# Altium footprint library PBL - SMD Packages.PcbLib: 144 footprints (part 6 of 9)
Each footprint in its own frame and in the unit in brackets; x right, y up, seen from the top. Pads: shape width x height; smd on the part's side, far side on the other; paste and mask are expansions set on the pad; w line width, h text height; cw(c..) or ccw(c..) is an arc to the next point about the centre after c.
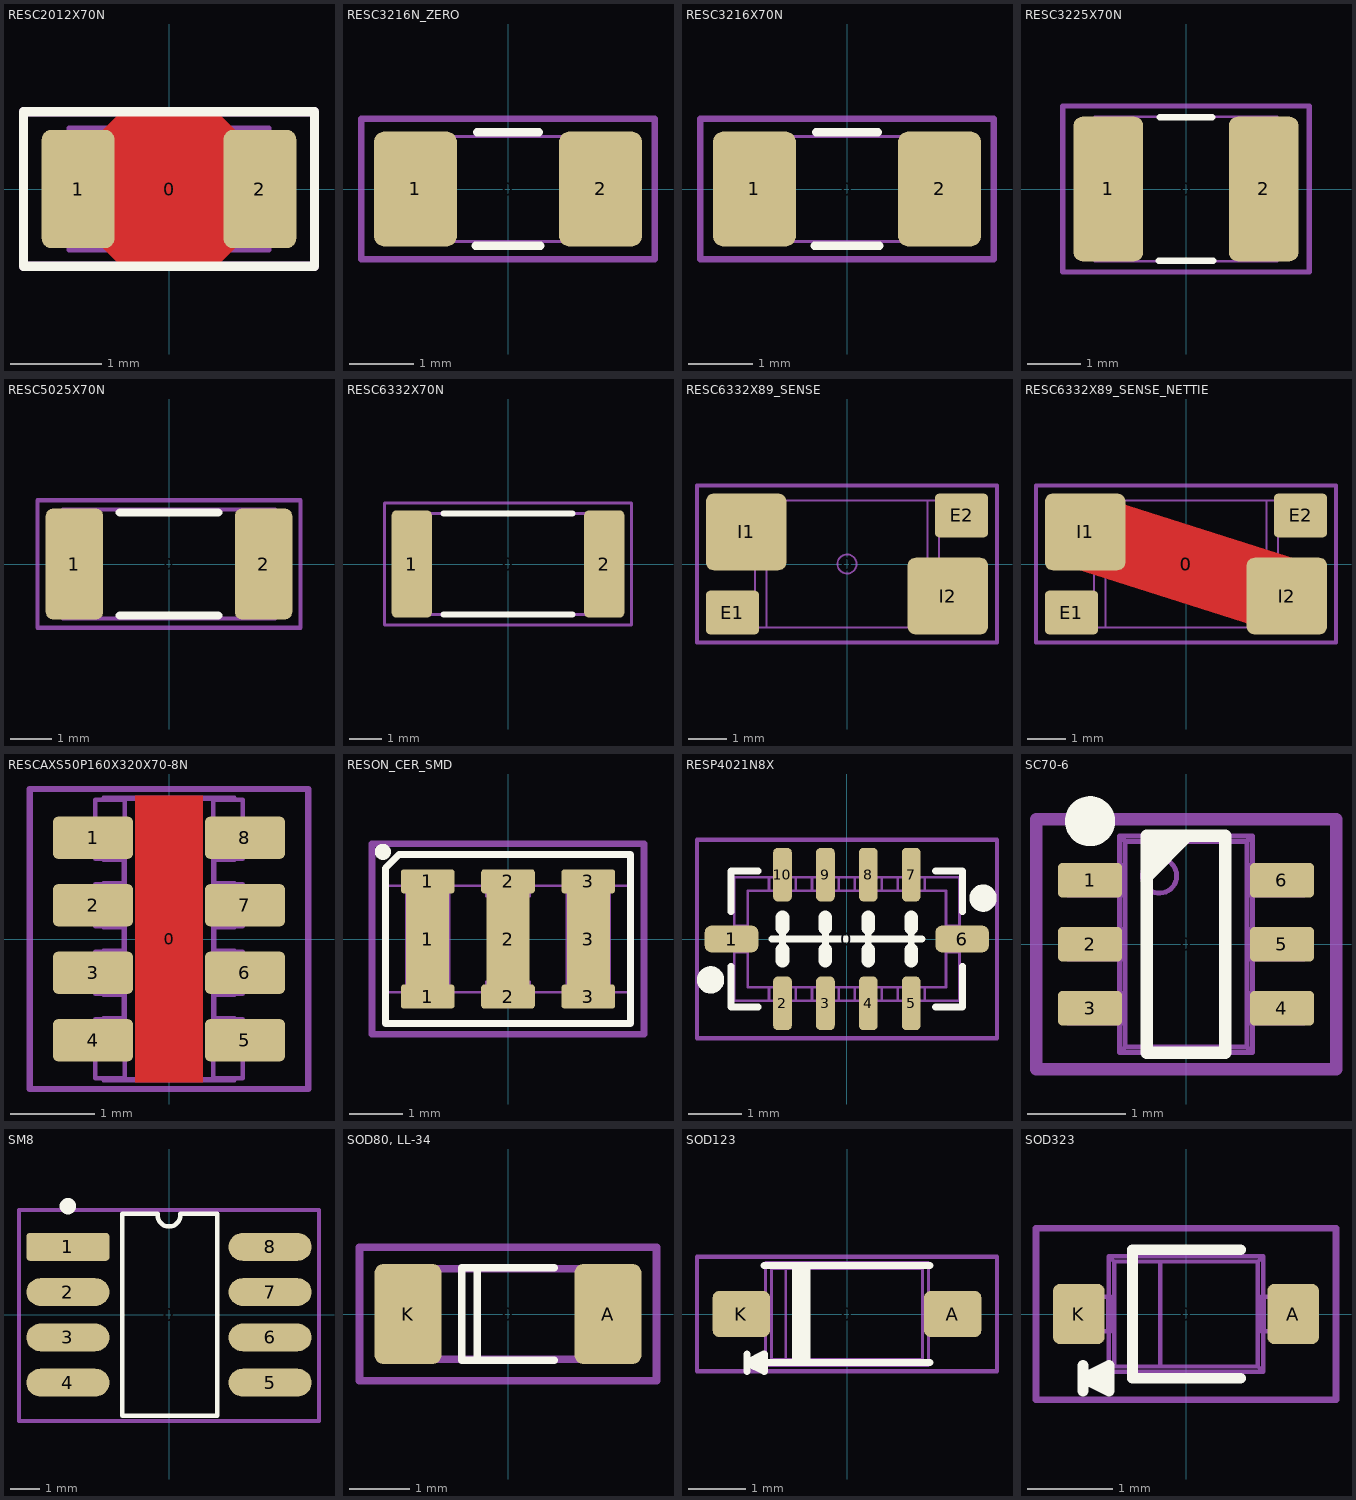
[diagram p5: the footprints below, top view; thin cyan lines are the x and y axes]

## RESC2012X70N [mm] "Chip Resistor, Body 2.0x1.2mm, EIA 0805, IPC Medium Density"
height 0.7
pads (3):
  round 0.254 on Mech15: 0(0,0)
  rrect25% 0.8x1.3 smd: 1(-1,0) 2(1,0)
Top Layer:
  pour cut-out: -0.725,0.65 -0.525,0.85 0.525,0.85 0.725,0.65 0.725,-0.65 0.525,-0.85 -0.525,-0.85 -0.725,-0.65
Top Overlay:
  lines w0.1: -1.6,-0.85 -1.6,0.85 1.6,0.85 1.6,-0.85 -1.6,-0.85
08 - Top ASM Des:
  text ".Designator" at -1.325,-0.325 h1
13 - 3D Top Side:
  lines w0.05: 0.6,-0.674 -0.6,-0.674 ; -0.6,-0.675 -0.6,0.675 -1.1,0.675 -1.1,-0.675 -0.6,-0.675 ; -0.6,-0.674 0.6,-0.674 ; 0.6,-0.675 0.6,0.675 ; 0.6,-0.675 1.1,-0.675 1.1,0.675 0.6,0.675 ; 0.6,0.674 -0.6,0.674 0.6,0.674
15 - Top Courtyards:
  lines w0.1: -1.6,-0.85 1.6,-0.85 1.6,0.85 -1.6,0.85 -1.6,-0.85
3D body "RES 0805 (2012 metric).STEP": height 0.69, standoff -0.01, extent -1.1,-0.675 1.1,0.675

## RESC3216N_ZERO [mm] "Chip Resistor, Body 3.2x1.6mm, 1206, IPC Medium Density"
height 0.7
pads (3):
  round 0.508 on Mech15: 0(0,0)
  rrect25% 1.3x1.8 smd: 1(-1.45,0) 2(1.45,0)
Top Overlay:
  lines w0.127: -0.508,-0.889 0.508,-0.889 ; -0.483,0.889 0.483,0.889
13 - 3D Top Side:
  lines w0.05: 1.025,-0.824 -1.025,-0.824 1.025,-0.824 ; -1.625,-0.825 -1.025,-0.825 -1.025,0.825 -1.625,0.825 -1.625,-0.825 ; -1.025,0.824 1.025,0.824 -1.025,0.824 ; 1.025,-0.825 1.025,0.825 1.625,0.825 1.625,-0.825 1.025,-0.825
15 - Top Courtyards:
  lines w0.1: -2.3,-1.1 -2.3,1.1 2.3,1.1 2.3,-1.1 -2.3,-1.1
3D body "RES 1206 (3216 metric).STEP": height 0.69, standoff -0.01, extent -1.625,-0.825 1.625,0.825

## RESC3216X70N [mm] "Chip Resistor, Body 3.2x1.6mm, EIA 1206, IPC Medium Density"
height 0.7
pads (3):
  round 0.508 on Mech15: 0(0,0)
  rrect25% 1.3x1.8 smd: 1(-1.45,0) 2(1.45,0)
Top Overlay:
  lines w0.127: -0.508,-0.889 0.508,-0.889 ; -0.483,0.889 0.483,0.889
13 - 3D Top Side:
  lines w0.05: 1.025,-0.824 -1.025,-0.824 1.025,-0.824 ; -1.625,-0.825 -1.025,-0.825 -1.025,0.825 -1.625,0.825 -1.625,-0.825 ; -1.025,0.824 1.025,0.824 -1.025,0.824 ; 1.025,-0.825 1.025,0.825 1.625,0.825 1.625,-0.825 1.025,-0.825
15 - Top Courtyards:
  lines w0.1: -2.3,-1.1 -2.3,1.1 2.3,1.1 2.3,-1.1 -2.3,-1.1
3D body "RES 1206 (3216 metric).STEP": height 0.69, standoff -0.01, extent -1.625,-0.825 1.625,0.825

## RESC3225X70N [mm] "Chip Resistor, Body 3.2x2.5mm, EIA 1210, IPC Medium Density"
height 0.7
pads (3):
  round 0.508 on Mech15: 0(0,0)
  rrect25% 1.3x2.7 smd: 1(-1.45,0) 2(1.45,0)
Top Overlay:
  lines w0.127: -0.508,-1.339 0.508,-1.339 ; -0.483,1.339 0.483,1.339
13 - 3D Top Side:
  lines w0.05: -1.7,-1.35 -1.1,-1.35 -1.1,1.35 -1.7,1.35 -1.7,-1.35 ; -1.1,-1.349 1.1,-1.349 -1.1,-1.349 ; -1.1,1.349 1.1,1.349 -1.1,1.349 ; 1.1,-1.35 1.1,1.35 1.7,1.35 1.7,-1.35 1.1,-1.35
15 - Top Courtyards:
  lines w0.1: -2.3,-1.55 -2.3,1.55 2.3,1.55 2.3,-1.55 -2.3,-1.55
3D body "RES 1210 (3225 metric).STEP": height 0.69, standoff -0.01, extent -1.7,-1.35 1.7,1.35

## RESC5025X70N [mm] "Chip Resistor, Body 5.0x2.5mm, 2010, IPC Medium Density"
height 0.7
pads (3):
  round 0.508 on Mech15: 0(0,0)
  rrect25% 1.4x2.7 smd: 1(-2.3,0) 2(2.3,0)
Top Overlay:
  lines w0.2: -1.2,-1.25 1.2,-1.25 ; -1.2,1.25 1.2,1.25
13 - 3D Top Side:
  lines w0.1: -2.575,-1.325 -2.575,1.325 2.575,1.325 2.575,-1.325 -2.575,-1.325
15 - Top Courtyards:
  lines w0.1: -3.2,-1.55 -3.2,1.55 3.2,1.55 3.2,-1.55 -3.2,-1.55
3D body "RES 2010 (5025 metric).STEP": height 0.69, standoff -0.01, extent -2.6,-1.35 2.6,1.35

## RESC6332X70N [mm] "Chip Resistor, Body 6.3x3.2mm, 2512, IPC Medium Density"
height 0.7
pads (3):
  round 1 on Mech15: 0(0,0)
  rrect25% 1.25x3.35 smd: 1(-3,0) 2(3,0)
Top Overlay:
  lines w0.2: -2,-1.575 2,-1.575 ; -2,1.575 2,1.575
13 - 3D Top Side:
  lines w0.1: -3.15,-1.575 -3.15,1.575 3.15,1.575 3.15,-1.575 -3.15,-1.575
15 - Top Courtyards:
  lines w0.1: -3.85,-1.9 -3.85,1.9 3.85,1.9 3.85,-1.9 -3.85,-1.9
3D body "RES 2512 (6432 metric).STEP": height 0.69, standoff -0.01, extent -3.3,-1.7 3.3,1.7

## RESC6332X89_SENSE [mil] "SMD Sense Resistor with Kelvin terminations, Body 6.3x3.2mm, 2512, IPC Medium Density"
height 35.04
pads (5):
  round 39.37 on Mech15: 0(0,0)
  rrect20% 55x45 smd paste-27.56: E1(-118,-50) E2(118,50)
  rrect20% 83x79 smd paste-43.31: I1(-104,33) I2(104,-33)
13 - 3D Top Side:
  circle w1.97: c0,0 r9.84
  lines w1.97: -82.91,-65.45 -82.91,65.45 ; 82.91,-65.45 82.91,65.45 ; -129.92,-65.45 -129.92,-31.99 -94.72,-31.99 -94.72,1.48 -129.92,1.48 -129.92,65.45 129.92,65.45 129.92,31.99 94.72,31.99 94.72,-1.48 129.92,-1.48 129.92,-65.45 -129.92,-65.45
15 - Top Courtyards:
  lines w3.94: -154.53,-80.71 -154.53,80.71 154.53,80.71 154.53,-80.71 -154.53,-80.71
3D body "RESC6332X89_119T_KELVIN.STEP": height 34.84, standoff 0, extent -129.91,-65.45 129.93,65.46

## RESC6332X89_SENSE_NETTIE [mil] "SMD Sense Resistor with Kelvin terminations, Body 6.3x3.2mm, 2512, IPC Medium Density"
height 35.04
pads (5):
  round 39.37 on Mech15: 0(0,0)
  rrect20% 55x45 smd paste-27.56: E1(-118,-50) E2(118,50)
  rrect20% 83x79 smd paste-43.31: I1(-104,33) I2(104,-33)
Top Layer:
  lines w78.74: -104,33 104,-33
13 - 3D Top Side:
  circle w1.97: c0,0 r9.84
  lines w1.97: -82.91,-65.45 -82.91,65.45 ; 82.91,-65.45 82.91,65.45 ; -129.92,-65.45 129.92,-65.45 129.92,-1.48 94.72,-1.48 94.72,31.99 129.92,31.99 129.92,65.45 -129.92,65.45 -129.92,1.48 -94.72,1.48 -94.72,-31.99 -129.92,-31.99 -129.92,-65.45
15 - Top Courtyards:
  lines w3.94: -154.53,-80.71 154.53,-80.71 154.53,80.71 -154.53,80.71 -154.53,-80.71
3D body "RESC6332X89_119T_KELVIN.STEP": height 34.84, standoff 0, extent -129.91,-65.45 129.93,65.46

## RESCAXS50P160X320X70-8N [mm] "Resistor Pack, Body 1.6x3.2mm, 4x0603, IPC Medium Density"
height 0.7
pads (9):
  round 0.254 on Mech15: 0(0,0)
  rrect25% 0.95x0.5 smd: 1(-0.9,1.2) 2(-0.9,0.4) 3(-0.9,-0.4) 4(-0.9,-1.2) 5(0.9,-1.2) 6(0.9,-0.4) 7(0.9,0.4) 8(0.9,1.2)
Top Layer:
  pour cut-out: -0.4,1.7 0.4,1.7 0.4,-1.7 -0.4,-1.7
Top Solder:
  region: 1.3,1.2 0.5,1.2 0.5,-1.2 1.3,-1.2
  rectangle: -1.3,-1.2 -0.5,1.2
13 - 3D Top Side:
  lines w0.05: -0.775,-1.65 -0.775,-1.675 0.775,-1.675 0.775,-1.65 ; -0.775,-0.95 -0.775,-0.938 -0.537,-0.938 -0.537,-0.663 -0.775,-0.663 -0.775,-0.65 ; -0.775,-0.15 -0.775,-0.138 -0.537,-0.138 -0.537,0.138 -0.775,0.138 -0.775,0.15 ; -0.775,0.65 -0.775,0.663 -0.537,0.663 -0.537,0.938 -0.775,0.938 -0.775,0.95 ; -0.775,1.65 -0.775,1.675 0.775,1.675 0.775,1.65 ; -0.525,-1.65 -0.875,-1.65 -0.875,-0.95 -0.525,-0.95 ; -0.525,-0.65 -0.875,-0.65 -0.875,-0.15 -0.525,-0.15 ; -0.525,0.15 -0.875,0.15 -0.875,0.65 -0.525,0.65 ; -0.525,0.95 -0.875,0.95 -0.875,1.65 -0.525,1.65 ; 0.525,-1.65 0.875,-1.65 0.875,-0.95 0.525,-0.95 ; 0.525,-0.65 0.875,-0.65 0.875,-0.15 0.525,-0.15 ; 0.525,0.15 0.875,0.15 0.875,0.65 0.525,0.65 ; 0.525,0.95 0.875,0.95 0.875,1.65 0.525,1.65 ; 0.775,-0.95 0.775,-0.938 0.537,-0.938 0.537,-0.663 0.775,-0.663 0.775,-0.65 ; 0.775,-0.15 0.775,-0.138 0.537,-0.138 0.537,0.138 0.775,0.138 0.775,0.15 ; 0.775,0.65 0.775,0.663 0.537,0.663 0.537,0.938 0.775,0.938 0.775,0.95 ; -0.525,-1.663 -0.525,1.663 0.525,1.663 0.525,-1.663 -0.525,-1.663
15 - Top Courtyards:
  lines w0.076: -1.651,-1.778 -1.651,1.778 1.651,1.778 1.651,-1.778 -1.651,-1.778
3D body "RESCAXS50P32X16X70-8N.STEP": height 0.7, standoff 0, extent -0.875,-1.675 0.875,1.675

## RESON_CER_SMD [mm] "SMD Ceramic Resonator 4.5mmx2mm"
height 1.2
pads (9):
  rrect25% 1x0.45 smd: 1(-1.499,-1.074) 1(-1.499,1.075) 2(0,-1.074) 2(0,1.075) 3(1.499,-1.074) 3(1.499,1.075)
  rrect25% 0.8x2.6 smd: 1(-1.499,0) 2(0,0) 3(1.499,0)
Top Overlay:
  circle w0.15: c-2.336,1.626 r0.075
  lines w0.127: -2.286,-1.575 2.286,-1.575 ; -2.286,-1.549 -2.286,1.321 -2.032,1.575 2.286,1.575 2.286,-1.549
13 - 3D Top Side:
  lines w0.05: -1.9,-0.995 -1.1,-0.995 ; -1.9,-0.995 -1.9,0.995 ; -1.9,-0.995 -2.25,-0.994 -2.25,0.994 -1.9,0.995 ; -1.9,0.995 -1.1,0.995 ; -1.1,-0.995 -1.1,0.995 ; -1.1,-0.995 -0.4,-0.994 ; -1.1,0.994 -0.4,0.995 ; -0.4,-0.995 0.4,-0.995 ; -0.4,-0.995 -0.4,-0.795 0.4,-0.795 0.4,-0.995 ; -0.4,0.995 0.4,0.995 ; -0.4,0.995 -0.4,0.795 0.4,0.795 0.4,0.995 ; 0.4,-0.995 1.1,-0.994 ; 0.4,0.994 1.1,0.995 ; 1.1,-0.995 1.9,-0.995 ; 1.1,-0.995 1.1,0.995 ; 1.1,0.995 1.9,0.995 ; 1.9,-0.995 1.9,0.995 ; 1.9,-0.995 2.25,-0.994 2.25,0.994 1.9,0.995
15 - Top Courtyards:
  lines w0.127: -2.54,-1.778 -2.54,1.778 2.54,1.778 2.54,-1.778 -2.54,-1.778
3D body "RESON_CERM.STEP": height 1.19, standoff 0, extent -2.25,-0.995 2.25,0.995

## RESP4021N8X [mm] "Resistor Pack, Body 4.0x2.1mm, 8 elements bussed, IPC Medium Density"
height 0.65
pads (11):
  round 0.508 on Mech15: 0(0,0)
  rrect50% 1x0.5 smd: 1(-2.15,0) 6(2.15,0)
  rrect50% 0.35x1 smd: 2(-1.2,-1.2) 3(-0.4,-1.2) 4(0.4,-1.2) 5(1.2,-1.2) 7(1.2,1.2) 8(0.4,1.2) 9(-0.4,1.2) 10(-1.2,1.2)
Top Overlay:
  circle w0.254: c-2.54,-0.762 r0.127
  circle w0.254: c2.54,0.762 r0.127
  lines w0.127: -2.159,-0.508 -2.159,-1.27 -1.651,-1.27 ; -2.159,0.508 -2.159,1.27 -1.651,1.27 ; -1.4,0 1.4,0 ; -1.2,-0.2 -1.2,0.2 ; -0.4,-0.2 -0.4,0.2 ; 0.4,-0.2 0.4,0.2 ; 1.2,-0.2 1.2,0.2 ; 1.651,-1.27 2.159,-1.27 2.159,-0.508 ; 1.651,1.27 2.159,1.27 2.159,0.508
  lines w0.254: -1.2,-0.4 -1.2,-0.2 ; -1.2,0.2 -1.2,0.4 ; -0.4,-0.4 -0.4,-0.2 ; -0.4,0.2 -0.4,0.4 ; 0.4,-0.4 0.4,-0.2 ; 0.4,0.2 0.4,0.4 ; 1.2,-0.4 1.2,-0.2 ; 1.2,0.2 1.2,0.4
13 - 3D Top Side:
  lines w0.05: -1.85,-0.25 -2.1,-0.25 ; -1.85,0.25 -2.1,0.25 ; -1.45,-0.9 -1.45,-1.15 ; -1.45,0.9 -1.45,1.15 ; -0.95,-0.9 -0.95,-1.15 ; -0.95,0.9 -0.95,1.15 ; -0.65,-1.149 -0.95,-1.15 ; -0.65,-0.9 -0.65,-1.15 -0.55,-1.15 cw(c-0.4,-1.15) -0.25,-1.15 -0.15,-1.15 ; -0.65,0.9 -0.65,1.15 -0.55,1.15 ccw(c-0.4,1.15) -0.25,1.15 -0.15,1.15 ; -0.65,1.149 -0.95,1.15 ; -0.15,-0.9 -0.15,-1.15 ; -0.15,0.9 -0.15,1.15 ; 0.15,-1.149 -0.15,-1.15 ; 0.15,-0.9 0.15,-1.15 0.25,-1.15 cw(c0.4,-1.15) 0.55,-1.15 0.65,-1.15 ; 0.15,0.9 0.15,1.15 0.25,1.15 ccw(c0.4,1.15) 0.55,1.15 0.65,1.15 ; 0.15,1.149 -0.15,1.15 ; 0.65,-0.9 0.65,-1.15 ; 0.65,0.9 0.65,1.15 ; 0.95,-1.149 0.65,-1.15 ; 0.95,-0.9 0.95,-1.15 1.05,-1.15 cw(c1.2,-1.15) 1.35,-1.15 1.45,-1.15 ; 0.95,0.9 0.95,1.15 1.05,1.15 ccw(c1.2,1.15) 1.35,1.15 1.45,1.15 ; 0.95,1.149 0.65,1.15 ; 1.45,-0.9 1.45,-1.15 ; 1.45,0.9 1.45,1.15 ; 1.85,-0.25 2.1,-0.25 ; 1.85,0.25 2.1,0.25 ; -2.1,-0.25 -2.1,-0.15 ccw(c-2.1,0) -2.1,0.15 -2.1,0.25 ; -2.1,-0.25 -2.099,-1.149 -1.45,-1.15 ; -2.1,0.25 -2.099,1.149 -1.45,1.15 ; -1.45,-1.15 -1.35,-1.15 cw(c-1.2,-1.15) -1.05,-1.15 -0.95,-1.15 ; -1.45,1.15 -1.35,1.15 ccw(c-1.2,1.15) -1.05,1.15 -0.95,1.15 ; 1.45,-1.15 2.099,-1.149 2.1,-0.25 ; 1.45,1.15 2.099,1.149 2.1,0.25 ; 2.1,-0.25 2.1,-0.15 cw(c2.1,0) 2.1,0.15 2.1,0.25 ; -1.85,-0.9 -1.85,0.9 1.85,0.9 1.85,-0.9 -1.85,-0.9
15 - Top Courtyards:
  lines w0.076: -2.794,-1.85 2.8,-1.85 2.8,1.85 -2.794,1.85 -2.794,-1.85
3D body "RES_ARRAY_EXBE.STEP": height 0.65, standoff 0, extent -2.1,-1.15 2.1,1.15

## SC70-6 [mm] "SC70-6; SOT-363"
height 1.6
pads (7):
  round 0.254 on Mech15: 0(0,0)
  rrect25% 0.65x0.35 smd: 1(-0.975,0.65) 2(-0.975,0) 3(-0.975,-0.65) 4(0.975,-0.65) 5(0.975,0) 6(0.975,0.65)
Top Overlay:
  circle w0.254: c-0.975,1.25 r0.127
  region: 0.1,1.1 -0.4,0.6 -0.4,1.1
  lines w0.127: -0.4,-1.1 -0.4,1.1 0.4,1.1 0.4,-1.1 -0.4,-1.1
13 - 3D Top Side:
  circle w0.05: c-0.27,0.695 r0.175
  lines w0.05: -1.028,-0.8 -1.028,-0.5 ; -1.028,-0.15 -1.028,0.15 ; -1.028,0.5 -1.028,0.8 ; -0.937,-0.8 -0.937,-0.5 ; -0.937,-0.15 -0.937,0.15 ; -0.937,0.5 -0.937,0.8 ; -0.925,-0.8 -0.925,-0.5 ; -0.925,-0.15 -0.925,0.15 ; -0.925,0.5 -0.925,0.8 ; 0.925,-0.8 0.925,-0.5 ; 0.925,-0.15 0.925,0.15 ; 0.925,0.5 0.925,0.8 ; 0.937,-0.8 0.937,-0.5 ; 0.937,-0.15 0.937,0.15 ; 0.937,0.5 0.937,0.8 ; 1.028,-0.8 1.028,-0.5 ; 1.028,-0.15 1.028,0.15 ; 1.028,0.5 1.028,0.8 ; -0.675,-1.1 0.675,-1.1 ; -0.675,-1.1 -0.675,1.1 ; -0.675,-1.1 -0.619,-1.044 ; -0.675,1.1 0.675,1.1 ; -0.675,1.1 -0.619,1.044 ; -0.619,-1.044 0.619,-1.044 ; -0.619,-1.044 -0.619,1.044 ; -0.619,1.044 0.619,1.044 ; 0.619,-1.044 0.675,-1.1 ; 0.619,-1.044 0.619,1.044 ; 0.619,1.044 0.675,1.1 ; 0.675,-1.1 0.675,1.1 ; -1.2,-0.8 -1.2,-0.5 -0.654,-0.5 -0.654,-0.8 -1.2,-0.8 ; -1.2,-0.15 -1.2,0.15 -0.654,0.15 -0.654,-0.15 -1.2,-0.15 ; -1.2,0.5 -1.2,0.8 -0.654,0.8 -0.654,0.5 -1.2,0.5 ; 0.654,-0.8 1.2,-0.8 1.2,-0.5 0.654,-0.5 0.654,-0.8 ; 0.654,-0.15 1.2,-0.15 1.2,0.15 0.654,0.15 0.654,-0.15 ; 0.654,0.5 1.2,0.5 1.2,0.8 0.654,0.8 0.654,0.5
15 - Top Courtyards:
  lines w0.127: -1.524,-1.27 -1.524,1.27 1.524,1.27 1.524,-1.27 -1.524,-1.27
3D body "SOT363.STEP": height 1.1, standoff 0, extent -1.2,-1.1 1.2,1.1

## SM8 [mil]
pads (9):
  round 39.37 on Mech15: 0(0,0)
  rrect25% 110x37 smd: 1(-134,90)
  oval 110x37 smd: 2(-134,30) 3(-134,-30) 4(-134,-90) 5(134,-90) 6(134,-30) 7(134,30) 8(134,90)
Top Overlay:
  circle w19.68: c-134,144 r1
  lines w6: -15,132 ccw(c0,132) 15,132 ; -15,134 -29,134 -62,134 -62,-134 64,-134 64,134 15,134
15 - Top Courtyards:
  lines w5: -198.82,-141 -198.82,139 198.82,139 198.82,-141 -198.82,-141
3D body "SM8.stp": height 66.93, standoff 0.09, extent -142.75,-129.92 142.76,129.92

## SOD80, LL-34 [mm] "Diode, MiniMELF"
height 1.6
pads (3):
  round 0.5 on Mech15: 0(0,0)
  rrect25% 1.1x1.65 smd: A(1.65,0) K(-1.65,0)
Top Overlay:
  lines w0.127: -0.508,-0.762 -0.508,0.762 ; 0.762,-0.762 -0.762,-0.762 -0.762,0.762 0.762,0.762
13 - 3D Top Side:
  lines w0.127: -1.8,-0.747 -1.8,0.747 1.8,0.747 1.8,-0.747 -1.8,-0.747
15 - Top Courtyards:
  lines w0.127: -2.45,-1.1 -2.45,1.1 2.45,1.1 2.45,-1.1 -2.45,-1.1
3D body "SOD80.stp": height 1.47, standoff -0.01, extent -1.8,-0.747 1.8,0.747

## SOD123 [mm] "SOD-123; 2 Leads; Body 2.7 x 1.6 mm, (LxW)"
height 1.35
pads (3):
  round 0.508 on Mech15: 0(0,0)
  rrect25% 1x0.8 smd: A(1.85,0) K(-1.85,0)
Top Overlay:
  lines w0.127: -1.75,-1 -1.75,-0.7 ; -1.45,0.85 1.45,0.85 ; -0.9,-0.85 -0.9,0.85 ; -0.8,-0.85 -0.8,0.85 ; -0.7,-0.85 -0.7,0.85 ; 1.448,-0.85 -1.45,-0.85 -1.75,-0.85 ; -1.75,-0.85 -1.45,-0.7 -1.45,-1 -1.75,-0.85
13 - 3D Top Side:
  lines w0.05: -1.766,-0.308 -1.766,0.308 ; -1.707,-0.308 -1.707,0.308 ; -1.517,-0.308 -1.517,0.308 ; -1.425,-0.308 -1.95,-0.308 -1.95,0.308 -1.425,0.308 ; 1.425,-0.308 1.95,-0.308 1.95,0.308 1.425,0.308 ; 1.517,-0.308 1.517,0.308 ; 1.707,-0.308 1.707,0.308 ; 1.766,-0.308 1.766,0.308 ; -1.425,-0.9 -1.425,0.9 ; -1.425,-0.9 -1.323,-0.798 ; -1.425,-0.9 1.425,-0.9 ; -1.425,0.9 1.425,0.9 ; -1.425,0.9 -1.323,0.798 ; -1.323,-0.798 -1.323,0.798 ; -1.323,-0.798 -1.072,-0.798 ; -1.323,0.798 -1.072,0.798 ; -1.072,-0.798 -1.072,0.798 ; -1.072,-0.798 1.322,-0.797 ; -1.072,0.798 1.322,0.797 ; 1.322,-0.797 1.425,-0.9 ; 1.322,-0.797 1.322,0.797 ; 1.322,0.797 1.425,0.9 ; 1.425,-0.9 1.425,0.9
15 - Top Courtyards:
  lines w0.076: -2.625,-1 -2.625,1 2.625,1 2.625,-1 -2.625,-1
3D body "SOD123.STEP": height 1.18, standoff 0, extent -1.95,-0.9 1.95,0.9

## SOD323 [mm] "SOD-323; 2 Leads; Body 1.8 x 1.35 mm, (LxW)"
height 1.15
pads (3):
  round 0.508 on Mech15: 0(0,0)
  rrect25% 0.6x0.7 smd: A(1.25,0) K(-1.25,0)
Top Overlay:
  lines w0.127: -1.2,-0.9 -1.2,-0.6 ; -0.9,-0.75 -1.2,-0.75 ; 0.635,-0.75 -0.625,-0.75 -0.625,0.75 0.635,0.75 ; -1.2,-0.75 -0.9,-0.9 -0.9,-0.6 -1.2,-0.75
13 - 3D Top Side:
  lines w0.05: -1.157,-0.2 -1.157,0.2 ; -1.11,-0.2 -1.11,0.2 ; -0.91,-0.2 -0.91,0.2 ; -0.9,-0.2 -0.9,-0.675 ; -0.9,0.2 -0.9,0.675 ; 0.9,-0.2 0.9,-0.675 ; 0.9,0.2 0.9,0.675 ; 0.91,-0.2 0.91,0.2 ; 1.11,-0.2 1.11,0.2 ; 1.157,-0.2 1.157,0.2 ; -0.9,-0.675 -0.838,-0.613 ; -0.9,-0.675 0.9,-0.675 ; -0.9,0.675 0.9,0.675 ; -0.9,0.675 -0.838,0.613 ; -0.838,-0.613 -0.838,0.613 ; -0.838,-0.613 -0.3,-0.613 ; -0.838,0.613 -0.3,0.613 ; -0.3,-0.613 -0.3,0.613 ; -0.3,-0.613 0.838,-0.613 ; -0.3,0.613 0.838,0.613 ; 0.838,-0.613 0.838,0.613 ; 0.838,-0.613 0.9,-0.675 ; 0.838,0.613 0.9,0.675 ; -1.3,-0.2 -1.3,0.2 -0.879,0.2 -0.879,-0.2 -1.3,-0.2 ; 0.879,-0.2 1.3,-0.2 1.3,0.2 0.879,0.2 0.879,-0.2
15 - Top Courtyards:
  lines w0.076: -1.75,-1 -1.75,1 1.75,1 1.75,-1 -1.75,-1
3D body "SOD323.STEP": height 1.1, standoff 0, extent -1.3,-0.675 1.3,0.675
